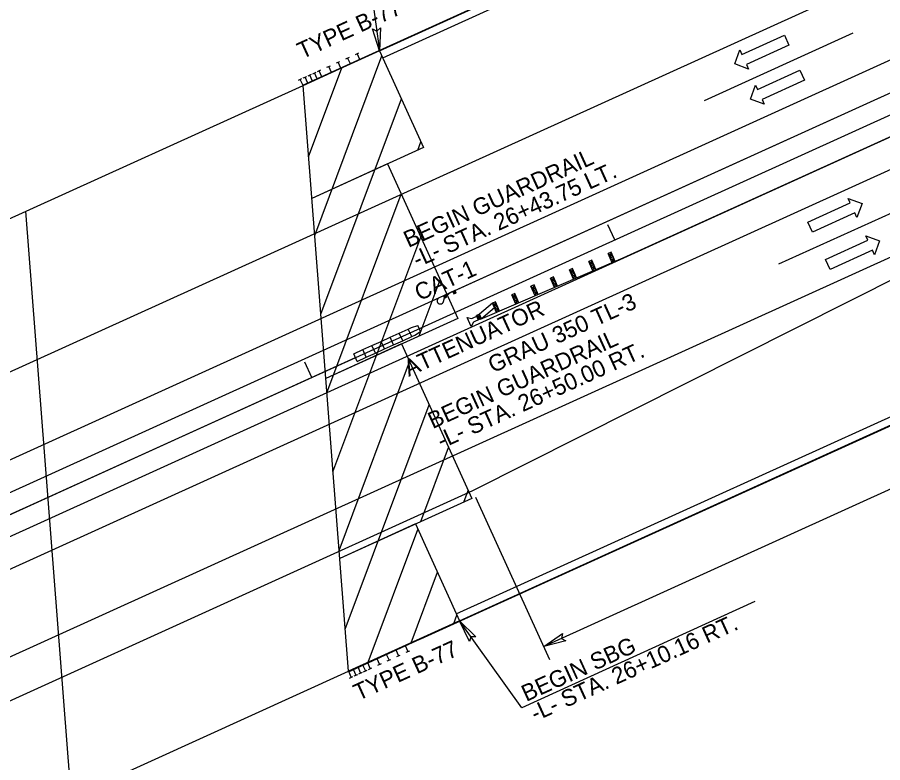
# Model space of a CAD drawing. Extents: x 2242984 to 2250974, y 661492 to 664681.
# Drawn here: x 2249051.2 to 2249311.2, y 663333.6 to 663557.7 of the extents above; entities that cross this region are included whole.
import ezdxf

# ---------------------------------------------------------------- set-up
doc = ezdxf.new("R2010")
doc.units = 0
for name, color, linetype in [('Prop Approach Slab', 7, 'Continuous'), ('Prop Approach Slab Hatching', 7, 'Continuous'), ('Prop Conc Barrier Precast Reinforced Single Face', 7, 'Continuous'), ('Prop Conc Shoulder Berm Gutter', 7, 'Continuous'), ('Prop Dimension', 7, 'Continuous'), ('Prop Dimension Text', 7, 'Continuous'), ('Prop DSN Text', 7, 'Continuous'), ('Prop EOT', 7, 'Continuous'), ('Prop Guardrail', 7, 'Continuous'), ('Prop Guardrail Anchor Unit CELL', 7, 'Continuous'), ('Prop Guardrail Attenuator CELL', 7, 'Continuous'), ('Prop Horizontal Alignment', 7, 'Continuous'), ('Prop Horizontal Alignment Tick Small', 7, 'Continuous'), ('Prop Lane Arrow CELL', 7, 'Continuous'), ('Prop Lane Lines', 7, 'Continuous'), ('Prop Paved Shoulder', 7, 'Continuous'), ('Prop Roadway Bridge', 7, 'Continuous'), ('Prop Structure Anchor Unit CELL', 7, 'Continuous'), ('Prop Terminator CELL', 7, 'Continuous'), ('Scratch_Level_6', 7, 'Continuous'), ('Scratch_Level_8', 7, 'Continuous')]:
    doc.layers.add(name, color=color, linetype=linetype)

msp = doc.modelspace()

# ---------------------------------------------------------------- linework, layer by layer
at = {"layer": 'Prop Approach Slab'}
for p, q in [((2249160.01, 663547.69), (2249137.03, 663537.25)), ((2249160.01, 663547.69), (2249173.25, 663518.55)), ((2249173.25, 663518.55), (2249139.66, 663503.29)), ((2249162.42, 663513.63), (2249139.66, 663503.29)), ((2249162.42, 663513.63), (2249183.52, 663467.2)), ((2249183.52, 663467.2), (2249143.85, 663449.18)), ((2249166.61, 663459.52), (2249143.85, 663449.18)), ((2249166.61, 663459.52), (2249187.71, 663413.09)), ((2249187.71, 663413.09), (2249148.05, 663395.07)), ((2249170.81, 663405.41), (2249148.05, 663395.07)), ((2249170.81, 663405.41), (2249184.04, 663376.28)), ((2249184.04, 663376.28), (2249150.68, 663361.12))]:
    msp.add_line(p, q, dxfattribs=at)
at = {"layer": 'Prop Approach Slab Hatching'}
for p, q in [((2249140.53, 663492.08), (2249160.73, 663546.11)), ((2249138.7, 663515.74), (2249148.73, 663542.56)), ((2249142.36, 663468.43), (2249166.59, 663533.22)), ((2249171.48, 663517.75), (2249172.44, 663520.33)), ((2249144.19, 663444.78), (2249166.55, 663504.56)), ((2249146.03, 663421.13), (2249172.4, 663491.67)), ((2249171.97, 663461.95), (2249178.26, 663478.77)), ((2249147.86, 663397.48), (2249169.05, 663454.16)), ((2249149.69, 663373.83), (2249174.91, 663441.27)), ((2249172.46, 663406.16), (2249180.76, 663428.37)), ((2249185.32, 663412), (2249186.62, 663415.48)), ((2249156.63, 663363.82), (2249171.56, 663403.76)), ((2249169.49, 663369.67), (2249177.41, 663390.87)), ((2249182.35, 663375.51), (2249183.27, 663377.97))]:
    msp.add_line(p, q, dxfattribs=at)
at = {"layer": 'Prop Conc Barrier Precast Reinforced Single Face'}
msp.add_line((2248886.12, 663334.3), (2249152.79, 663455.44), dxfattribs=at)
at = {"layer": 'Prop Conc Shoulder Berm Gutter'}
for p, q in [((2249160.98, 663545.56), (2249407.42, 663657.51)), ((2249183.08, 663378.4), (2249474.15, 663510.62))]:
    msp.add_line(p, q, dxfattribs=at)
at = {"layer": 'Prop Dimension'}
for p, q in [((2249482.48, 663492.62), (2249209.34, 663368.55)), ((2249211.16, 663364.55), (2249189, 663413.34))]:
    msp.add_line(p, q, dxfattribs=at)
at = {"layer": 'Prop DSN Text'}
for p, q in [((2249155.21, 663582.96), (2249160.01, 663547.69)), ((2249272.83, 663382.07), (2249202.78, 663350.15)), ((2249202.78, 663350.15), (2249184.04, 663376.28))]:
    msp.add_line(p, q, dxfattribs=at)
at = {"layer": 'Prop EOT'}
for p, q in [((2248850.37, 663360.9), (2249423.96, 663621.46)), ((2248200.21, 663039.2), (2249433.89, 663599.6)), ((2248212.61, 663011.89), (2249446.3, 663572.29)), ((2249188.04, 663415.44), (2249456.22, 663550.44)), ((2248401.88, 663058.32), (2249188.04, 663415.44))]:
    msp.add_line(p, q, dxfattribs=at)
at = {"layer": 'Prop Guardrail'}
for p, q in [((2249182.68, 663475.61), (2249637.91, 663682.4)), ((2249642.88, 663671.47), (2249233.17, 663485.36)), ((2249182.68, 663475.61), (2249592.39, 663661.72)), ((2249406.59, 663659.7), (2249154.1, 663545)), ((2249167.75, 663368.88), (2249475.25, 663508.56))]:
    msp.add_line(p, q, dxfattribs=at)
at = {"layer": 'Prop Guardrail Anchor Unit CELL'}
for p, q in [((2249229.64, 663487.11), (2249228.73, 663486.72)), ((2249229.64, 663487.11), (2249228.73, 663486.72)), ((2249229.91, 663483.96), (2249228.73, 663486.72)), ((2249228.73, 663486.72), (2249230.24, 663485.73)), ((2249229.91, 663483.96), (2249228.73, 663486.72)), ((2249228.73, 663486.72), (2249230.24, 663485.73)), ((2249229.32, 663485.34), (2249229.64, 663487.11)), ((2249229.32, 663485.34), (2249229.64, 663487.11)), ((2249230.83, 663484.36), (2249229.64, 663487.11)), ((2249230.83, 663484.36), (2249229.64, 663487.11)), ((2249233.17, 663485.36), (2249190.22, 663466.88)), ((2249233.17, 663485.36), (2249190.22, 663466.88)), ((2249223.84, 663484.67), (2249222.92, 663484.27)), ((2249223.84, 663484.67), (2249222.92, 663484.27)), ((2249224.12, 663481.47), (2249222.92, 663484.27)), ((2249222.92, 663484.27), (2249224.44, 663483.27)), ((2249224.12, 663481.47), (2249222.92, 663484.27)), ((2249222.92, 663484.27), (2249224.44, 663483.27)), ((2249223.52, 663482.87), (2249223.84, 663484.67)), ((2249223.52, 663482.87), (2249223.84, 663484.67)), ((2249225.04, 663481.86), (2249223.84, 663484.67)), ((2249225.04, 663481.86), (2249223.84, 663484.67)), ((2249230.24, 663485.73), (2249229.32, 663485.34)), ((2249230.24, 663485.73), (2249229.32, 663485.34)), ((2249229.91, 663483.96), (2249229.32, 663485.34)), ((2249229.32, 663485.34), (2249230.83, 663484.36)), ((2249229.91, 663483.96), (2249229.32, 663485.34)), ((2249229.32, 663485.34), (2249230.83, 663484.36)), ((2249230.24, 663485.73), (2249229.91, 663483.96)), ((2249230.24, 663485.73), (2249229.91, 663483.96)), ((2249230.83, 663484.36), (2249229.91, 663483.96)), ((2249230.83, 663484.36), (2249229.91, 663483.96)), ((2249218.05, 663482.17), (2249217.13, 663481.78)), ((2249218.05, 663482.17), (2249217.13, 663481.78)), ((2249218.34, 663478.98), (2249217.13, 663481.78)), ((2249217.13, 663481.78), (2249218.65, 663480.77)), ((2249218.34, 663478.98), (2249217.13, 663481.78)), ((2249217.13, 663481.78), (2249218.65, 663480.77)), ((2249217.73, 663480.38), (2249218.05, 663482.17)), ((2249217.73, 663480.38), (2249218.05, 663482.17)), ((2249219.25, 663479.37), (2249218.05, 663482.17)), ((2249219.25, 663479.37), (2249218.05, 663482.17)), ((2249224.44, 663483.27), (2249223.52, 663482.87)), ((2249224.44, 663483.27), (2249223.52, 663482.87)), ((2249225.04, 663481.86), (2249223.52, 663482.87)), ((2249225.04, 663481.86), (2249223.52, 663482.87)), ((2249224.44, 663483.27), (2249224.12, 663481.47)), ((2249224.44, 663483.27), (2249224.12, 663481.47)), ((2249212.27, 663479.67), (2249211.35, 663479.28)), ((2249212.27, 663479.67), (2249211.35, 663479.28)), ((2249212.55, 663476.49), (2249211.35, 663479.28)), ((2249211.35, 663479.28), (2249212.87, 663478.28)), ((2249212.55, 663476.49), (2249211.35, 663479.28)), ((2249211.35, 663479.28), (2249212.87, 663478.28)), ((2249211.95, 663477.88), (2249212.27, 663479.67)), ((2249211.95, 663477.88), (2249212.27, 663479.67)), ((2249213.47, 663476.88), (2249212.27, 663479.67)), ((2249213.47, 663476.88), (2249212.27, 663479.67)), ((2249218.65, 663480.77), (2249217.73, 663480.38)), ((2249218.65, 663480.77), (2249217.73, 663480.38)), ((2249219.25, 663479.37), (2249217.73, 663480.38)), ((2249219.25, 663479.37), (2249217.73, 663480.38)), ((2249218.65, 663480.77), (2249218.34, 663478.98)), ((2249218.65, 663480.77), (2249218.34, 663478.98)), ((2249206.44, 663477.27), (2249205.52, 663476.88)), ((2249206.44, 663477.27), (2249205.52, 663476.88)), ((2249206.76, 663474), (2249205.52, 663476.88)), ((2249205.52, 663476.88), (2249207.06, 663475.83)), ((2249206.76, 663474), (2249205.52, 663476.88)), ((2249205.52, 663476.88), (2249207.06, 663475.83)), ((2249206.14, 663475.44), (2249206.44, 663477.27)), ((2249206.14, 663475.44), (2249206.44, 663477.27)), ((2249207.06, 663475.83), (2249206.14, 663475.44)), ((2249207.06, 663475.83), (2249206.14, 663475.44)), ((2249207.68, 663474.39), (2249206.44, 663477.27)), ((2249207.68, 663474.39), (2249206.44, 663477.27)), ((2249207.06, 663475.83), (2249206.76, 663474)), ((2249207.06, 663475.83), (2249206.76, 663474)), ((2249212.87, 663478.28), (2249211.95, 663477.88)), ((2249212.87, 663478.28), (2249211.95, 663477.88)), ((2249213.47, 663476.88), (2249211.95, 663477.88)), ((2249213.47, 663476.88), (2249211.95, 663477.88)), ((2249212.87, 663478.28), (2249212.55, 663476.49)), ((2249212.87, 663478.28), (2249212.55, 663476.49)), ((2249213.47, 663476.88), (2249212.55, 663476.49)), ((2249213.47, 663476.88), (2249212.55, 663476.49)), ((2249179.45, 663474.14), (2249177.89, 663473.43)), ((2249179.45, 663474.14), (2249177.89, 663473.43)), ((2249179.85, 663474.32), (2249179.21, 663474.03)), ((2249179.85, 663474.32), (2249179.21, 663474.03)), ((2249179.21, 663474.03), (2249179.55, 663473.3)), ((2249179.21, 663474.03), (2249180.18, 663473.59)), ((2249179.21, 663474.03), (2249179.55, 663473.3)), ((2249179.21, 663474.03), (2249180.18, 663473.59)), ((2249179.27, 663472.32), (2249179.5, 663473.39)), ((2249179.27, 663472.32), (2249179.5, 663473.39)), ((2249179.33, 663474.09), (2249179.45, 663474.14)), ((2249179.33, 663474.09), (2249179.45, 663474.14)), ((2249182.68, 663475.61), (2249179.45, 663474.14)), ((2249182.68, 663475.61), (2249179.45, 663474.14)), ((2249179.85, 663474.32), (2249179.55, 663473.3)), ((2249179.85, 663474.32), (2249179.55, 663473.3)), ((2249179.55, 663473.3), (2249180.18, 663473.59)), ((2249179.55, 663473.3), (2249180.18, 663473.59)), ((2249179.7, 663473.81), (2249181.26, 663474.96)), ((2249179.7, 663473.81), (2249181.26, 663474.96)), ((2249180.18, 663473.59), (2249179.85, 663474.32)), ((2249180.18, 663473.59), (2249179.85, 663474.32)), ((2249182.68, 663475.61), (2249182.04, 663475.32)), ((2249182.68, 663475.61), (2249182.04, 663475.32)), ((2249182.04, 663475.32), (2249182.38, 663474.58)), ((2249182.04, 663475.32), (2249183.01, 663474.87)), ((2249182.04, 663475.32), (2249182.38, 663474.58)), ((2249182.04, 663475.32), (2249183.01, 663474.87)), ((2249182.68, 663475.61), (2249182.38, 663474.58)), ((2249182.68, 663475.61), (2249182.38, 663474.58)), ((2249182.38, 663474.58), (2249183.01, 663474.87)), ((2249182.38, 663474.58), (2249183.01, 663474.87)), ((2249183.01, 663474.87), (2249182.68, 663475.61)), ((2249183.01, 663474.87), (2249182.68, 663475.61)), ((2249200.7, 663474.66), (2249199.79, 663474.26)), ((2249200.7, 663474.66), (2249199.79, 663474.26)), ((2249200.97, 663471.51), (2249199.79, 663474.26)), ((2249199.79, 663474.26), (2249201.3, 663473.28)), ((2249200.97, 663471.51), (2249199.79, 663474.26)), ((2249199.79, 663474.26), (2249201.3, 663473.28)), ((2249200.38, 663472.88), (2249200.7, 663474.66)), ((2249200.38, 663472.88), (2249200.7, 663474.66)), ((2249201.3, 663473.28), (2249200.38, 663472.88)), ((2249201.3, 663473.28), (2249200.38, 663472.88)), ((2249201.89, 663471.9), (2249200.7, 663474.66)), ((2249201.89, 663471.9), (2249200.7, 663474.66)), ((2249201.3, 663473.28), (2249200.97, 663471.51)), ((2249201.3, 663473.28), (2249200.97, 663471.51)), ((2249207.68, 663474.39), (2249206.14, 663475.44)), ((2249207.68, 663474.39), (2249206.14, 663475.44)), ((2249193.97, 663471.83), (2249190.09, 663468.46)), ((2249193.97, 663471.83), (2249190.09, 663468.46)), ((2249194.89, 663472.22), (2249193.97, 663471.83)), ((2249194.89, 663472.22), (2249193.97, 663471.83)), ((2249195.18, 663469.02), (2249193.97, 663471.83)), ((2249193.97, 663471.83), (2249195.5, 663470.82)), ((2249195.18, 663469.02), (2249193.97, 663471.83)), ((2249193.97, 663471.83), (2249195.5, 663470.82)), ((2249194.58, 663470.42), (2249194.89, 663472.22)), ((2249194.58, 663470.42), (2249194.89, 663472.22)), ((2249195.5, 663470.82), (2249194.58, 663470.42)), ((2249195.5, 663470.82), (2249194.58, 663470.42)), ((2249196.1, 663469.41), (2249194.89, 663472.22)), ((2249196.1, 663469.41), (2249194.89, 663472.22)), ((2249195.5, 663470.82), (2249195.18, 663469.02)), ((2249195.5, 663470.82), (2249195.18, 663469.02)), ((2249201.89, 663471.9), (2249200.38, 663472.88)), ((2249201.89, 663471.9), (2249200.38, 663472.88)), ((2249187.8, 663467.21), (2249189.66, 663468.05)), ((2249187.8, 663467.21), (2249189.66, 663468.05)), ((2249190.09, 663468.46), (2249189.17, 663468.06)), ((2249190.09, 663468.46), (2249189.17, 663468.06)), ((2249189.76, 663466.68), (2249189.17, 663468.06)), ((2249189.17, 663468.06), (2249190.68, 663467.08)), ((2249189.76, 663466.68), (2249189.17, 663468.06)), ((2249189.17, 663468.06), (2249190.68, 663467.08)), ((2249190.09, 663468.46), (2249189.63, 663468.26)), ((2249190.09, 663468.46), (2249189.63, 663468.26)), ((2249189.66, 663468.05), (2249189.91, 663467.49)), ((2249189.66, 663468.05), (2249189.91, 663467.49)), ((2249189.76, 663466.68), (2249190.09, 663468.46)), ((2249189.76, 663466.68), (2249190.09, 663468.46)), ((2249190.68, 663467.08), (2249190.09, 663468.46)), ((2249190.68, 663467.08), (2249190.09, 663468.46)), ((2249194.58, 663470.42), (2249190.68, 663467.08)), ((2249194.58, 663470.42), (2249190.68, 663467.08)), ((2249196.1, 663469.41), (2249194.58, 663470.42)), ((2249196.1, 663469.41), (2249194.58, 663470.42)), ((2249187.58, 663464.82), (2249186.37, 663467.5)), ((2249186.37, 663467.5), (2249187.8, 663467.21)), ((2249187.58, 663464.82), (2249186.37, 663467.5)), ((2249186.37, 663467.5), (2249187.8, 663467.21)), ((2249188.3, 663466.09), (2249187.58, 663464.82)), ((2249188.3, 663466.09), (2249187.58, 663464.82)), ((2249190.16, 663466.94), (2249188.3, 663466.09)), ((2249190.16, 663466.94), (2249188.3, 663466.09)), ((2249189.91, 663467.49), (2249190.16, 663466.94)), ((2249189.91, 663467.49), (2249190.16, 663466.94))]:
    msp.add_line(p, q, dxfattribs=at)
msp.add_ellipse((2249178.3, 663472.53), major_axis=(0.411, -0.904), ratio=0.995379, start_param=3.141593, end_param=7.214552, dxfattribs=at)
msp.add_ellipse((2249178.3, 663472.53), major_axis=(0.411, -0.904), ratio=0.995379, start_param=3.141593, end_param=7.214552, dxfattribs=at)
at = {"layer": 'Prop Guardrail Attenuator CELL'}
for p, q in [((2249163.2, 663461.54), (2249165.93, 663462.78)), ((2249165.93, 663462.78), (2249168.66, 663464.02)), ((2249166.97, 663460.51), (2249165.93, 663462.78)), ((2249168.66, 663464.02), (2249169.58, 663464.44)), ((2249169.7, 663461.75), (2249168.66, 663464.02)), ((2249169.58, 663464.44), (2249171.5, 663465.04)), ((2249170.61, 663462.16), (2249172.33, 663463.22)), ((2249171.91, 663464.13), (2249171.5, 663465.04)), ((2249172.33, 663463.22), (2249171.91, 663464.13)), ((2249157.74, 663459.06), (2249160.47, 663460.3)), ((2249160.47, 663460.3), (2249163.2, 663461.54)), ((2249161.5, 663458.03), (2249160.47, 663460.3)), ((2249164.24, 663459.27), (2249163.2, 663461.54)), ((2249164.24, 663459.27), (2249166.97, 663460.51)), ((2249166.97, 663460.51), (2249169.7, 663461.75)), ((2249169.7, 663461.75), (2249170.61, 663462.16)), ((2249152.28, 663456.58), (2249155.01, 663457.82)), ((2249155.01, 663457.82), (2249157.74, 663459.06)), ((2249156.04, 663455.54), (2249155.01, 663457.82)), ((2249158.77, 663456.78), (2249157.74, 663459.06)), ((2249158.77, 663456.78), (2249161.5, 663458.03)), ((2249161.5, 663458.03), (2249164.24, 663459.27)), ((2249153.31, 663454.3), (2249152.28, 663456.58)), ((2249153.31, 663454.3), (2249156.04, 663455.54)), ((2249156.04, 663455.54), (2249158.77, 663456.78))]:
    msp.add_line(p, q, dxfattribs=at)
at = {"layer": 'Prop Horizontal Alignment'}
msp.add_line((2247500.8, 662705.02), (2249793.08, 663746.29), dxfattribs=at)
at = {"layer": 'Prop Horizontal Alignment Tick Small'}
for p, q in [((2249230.68, 663490.82), (2249228.62, 663495.38)), ((2249139.64, 663449.46), (2249137.57, 663454.02))]:
    msp.add_line(p, q, dxfattribs=at)
at = {"layer": 'Prop Lane Arrow CELL'}
for p, q in [((2249268.92, 663546.55), (2249281.66, 663552.35)), ((2249281.66, 663552.35), (2249283.03, 663549.35)), ((2249283.03, 663549.35), (2249270.29, 663543.54)), ((2249266.76, 663543.69), (2249268.3, 663547.91)), ((2249268.3, 663547.91), (2249268.92, 663546.55)), ((2249270.91, 663542.18), (2249266.76, 663543.69)), ((2249270.29, 663543.54), (2249270.91, 663542.18)), ((2249273.61, 663535.98), (2249286.35, 663541.79)), ((2249286.35, 663541.79), (2249287.72, 663538.79)), ((2249287.72, 663538.79), (2249274.98, 663532.98)), ((2249271.45, 663533.13), (2249272.99, 663537.35)), ((2249272.99, 663537.35), (2249273.61, 663535.98)), ((2249275.6, 663531.62), (2249271.45, 663533.13)), ((2249274.98, 663532.98), (2249275.6, 663531.62)), ((2249288.73, 663496.11), (2249301.47, 663501.91)), ((2249301.47, 663501.91), (2249300.85, 663503.28)), ((2249300.85, 663503.28), (2249305, 663501.76)), ((2249305, 663501.76), (2249303.46, 663497.55)), ((2249302.84, 663498.91), (2249290.1, 663493.11)), ((2249303.46, 663497.55), (2249302.84, 663498.91)), ((2249290.1, 663493.11), (2249288.73, 663496.11)), ((2249306.76, 663490.68), (2249306.14, 663492.05)), ((2249306.14, 663492.05), (2249310.29, 663490.53)), ((2249294.02, 663484.88), (2249306.76, 663490.68)), ((2249310.29, 663490.53), (2249308.75, 663486.31)), ((2249308.13, 663487.68), (2249295.39, 663481.87)), ((2249308.75, 663486.31), (2249308.13, 663487.68)), ((2249295.39, 663481.87), (2249294.02, 663484.88))]:
    msp.add_line(p, q, dxfattribs=at)
at = {"layer": 'Prop Lane Lines'}
for p, q in [((2249257.69, 663532.75), (2249302.32, 663553.02)), ((2248759.04, 663233.74), (2249456.25, 663550.45)), ((2249280.02, 663483.58), (2249324.65, 663503.85))]:
    msp.add_line(p, q, dxfattribs=at)
at = {"layer": 'Prop Paved Shoulder'}
for p, q in [((2249160.01, 663547.69), (2249406.59, 663659.7)), ((2248894.79, 663344.83), (2249437.63, 663591.42)), ((2248895.78, 663332.1), (2249442.57, 663580.48)), ((2249184.04, 663376.28), (2249475.25, 663508.56))]:
    msp.add_line(p, q, dxfattribs=at)
at = {"layer": 'Prop Roadway Bridge'}
for p, q in [((2248888.56, 663424.38), (2249137.03, 663537.25)), ((2249150.68, 663361.12), (2249137.03, 663537.25)), ((2249067.41, 663323.3), (2249053.77, 663499.42)), ((2248902.21, 663248.25), (2249150.68, 663361.12))]:
    msp.add_line(p, q, dxfattribs=at)
at = {"layer": 'Prop Structure Anchor Unit CELL'}
for p, q in [((2249152.75, 663546.58), (2249153.8, 663547.06)), ((2249154.1, 663545), (2249153.27, 663546.82)), ((2249137.03, 663537.25), (2249154.1, 663545)), ((2249147.06, 663544), (2249148.11, 663544.47)), ((2249148.41, 663542.42), (2249147.58, 663544.24)), ((2249149.91, 663545.29), (2249150.95, 663545.77)), ((2249151.26, 663543.71), (2249150.43, 663545.53)), ((2249139.95, 663540.77), (2249140.99, 663541.24)), ((2249141.3, 663539.18), (2249140.47, 663541.01)), ((2249141.37, 663541.42), (2249142.42, 663541.89)), ((2249142.72, 663539.83), (2249141.89, 663541.65)), ((2249144.22, 663542.71), (2249145.26, 663543.18)), ((2249145.57, 663541.12), (2249144.74, 663542.94)), ((2249135.68, 663538.83), (2249136.72, 663539.3)), ((2249137.03, 663537.25), (2249136.2, 663539.07)), ((2249137.1, 663539.48), (2249138.15, 663539.95)), ((2249138.45, 663537.89), (2249137.63, 663539.71)), ((2249138.53, 663540.12), (2249139.57, 663540.6)), ((2249139.88, 663538.54), (2249139.05, 663540.36)), ((2249150.68, 663361.12), (2249167.75, 663368.88)), ((2249164.9, 663367.58), (2249165.73, 663365.76)), ((2249167.75, 663368.88), (2249168.57, 663367.05)), ((2249168.05, 663366.82), (2249169.1, 663367.29)), ((2249159.21, 663365), (2249160.04, 663363.18)), ((2249162.06, 663366.29), (2249162.88, 663364.47)), ((2249162.36, 663364.23), (2249163.41, 663364.71)), ((2249165.21, 663365.52), (2249166.25, 663366)), ((2249152.1, 663361.77), (2249152.93, 663359.95)), ((2249153.52, 663362.41), (2249154.35, 663360.59)), ((2249154.94, 663363.06), (2249155.77, 663361.24)), ((2249155.25, 663361), (2249156.29, 663361.48)), ((2249156.37, 663363.71), (2249157.19, 663361.88)), ((2249156.67, 663361.65), (2249157.72, 663362.12)), ((2249159.52, 663362.94), (2249160.56, 663363.41)), ((2249150.68, 663361.12), (2249151.5, 663359.3)), ((2249150.98, 663359.06), (2249152.02, 663359.54)), ((2249152.4, 663359.71), (2249153.45, 663360.18)), ((2249153.83, 663360.36), (2249154.87, 663360.83))]:
    msp.add_line(p, q, dxfattribs=at)
at = {"layer": 'Prop Terminator CELL'}
for points in [[(2249160.26, 663554.53), (2249160.01, 663547.69), (2249157.91, 663554.25), (2249159.22, 663553.56)], [(2249187.03, 663370.11), (2249184.04, 663376.28), (2249188.97, 663371.46), (2249187.49, 663371.46)], [(2249215.97, 663370.28), (2249209.34, 663368.55), (2249215.03, 663372.45), (2249214.74, 663371)]]:
    msp.add_lwpolyline(points, close=True, dxfattribs=at)
at = {"layer": 'Scratch_Level_6'}
for p, q in [((2249155.72, 663545.84), (2249406.56, 663659.79)), ((2249136.93, 663537.31), (2249155.72, 663545.84)), ((2249167.72, 663368.76), (2249475.29, 663508.47)), ((2249150.65, 663361), (2249167.72, 663368.76))]:
    msp.add_line(p, q, dxfattribs=at)
at = {"layer": 'Scratch_Level_8'}
for p, q in [((2249158.7, 663547.19), (2249406.56, 663659.78)), ((2249172.45, 663370.91), (2249475.29, 663508.48))]:
    msp.add_line(p, q, dxfattribs=at)

# ---------------------------------------------------------------- texts
at = {"layer": 'Prop Dimension Text'}
for s, p in [('BEGIN GUARDRAIL', (2249168.69, 663488.37)), ('-L- STA. 26+43.75 LT.', (2249171.4, 663482.4)), ('BEGIN GUARDRAIL', (2249175.99, 663433.91)), ('-L- STA. 26+50.00 RT.', (2249178.7, 663427.94))]:
    msp.add_text(s, height=5, rotation=24.4301, dxfattribs=at).set_placement(p)
at = {"layer": 'Prop DSN Text'}
for s, p in [('-L- STA. 26+10.16 RT.', (2249206.83, 663345.93)), ('BEGIN SBG', (2249204.11, 663351.89))]:
    msp.add_text(s, height=5, rotation=24.4979, dxfattribs=at).set_placement(p)
at = {"layer": 'Prop Guardrail Anchor Unit CELL'}
for s, p in [('CAT-1', (2249171.99, 663472.39)), ('GRAU 350 TL-3', (2249194.06, 663450.69))]:
    msp.add_text(s, height=5, rotation=24.4301, dxfattribs=at).set_placement(p)
at = {"layer": 'Prop Guardrail Attenuator CELL'}
msp.add_text('ATTENUATOR', height=5, rotation=24.4979, dxfattribs=at).set_placement((2249168.78, 663449.62))
at = {"layer": 'Prop Structure Anchor Unit CELL'}
for p in [(2249136.74, 663545.1), (2249153.66, 663352.19)]:
    msp.add_text('TYPE B-77', height=5, rotation=24.4979, dxfattribs=at).set_placement(p)

doc.saveas('drawing.dxf')
